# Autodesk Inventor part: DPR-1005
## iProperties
Created: 2004-11
Part Number: DPR-1005
Cost Center: 0 lbmass
Document SubType Name: Modeling
Designer: busseym
Manufacturer: Standard
Standards Organization: Custom
Stock Number: DPR-1005
Density: 1 g/cm^3
CAGE: 1LJX3
Dept. ID: Product Design
Description #2: ---
Finish #1: ---
Finish #2: ---
Material ID: ---
Project Number: ---
Author: busseym
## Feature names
1. Extrusion1
2. Extrusion2
3. Extrusion4
4. Circular Pattern1
5. Mirror1
6. Extrusion3
7. Mirror2
